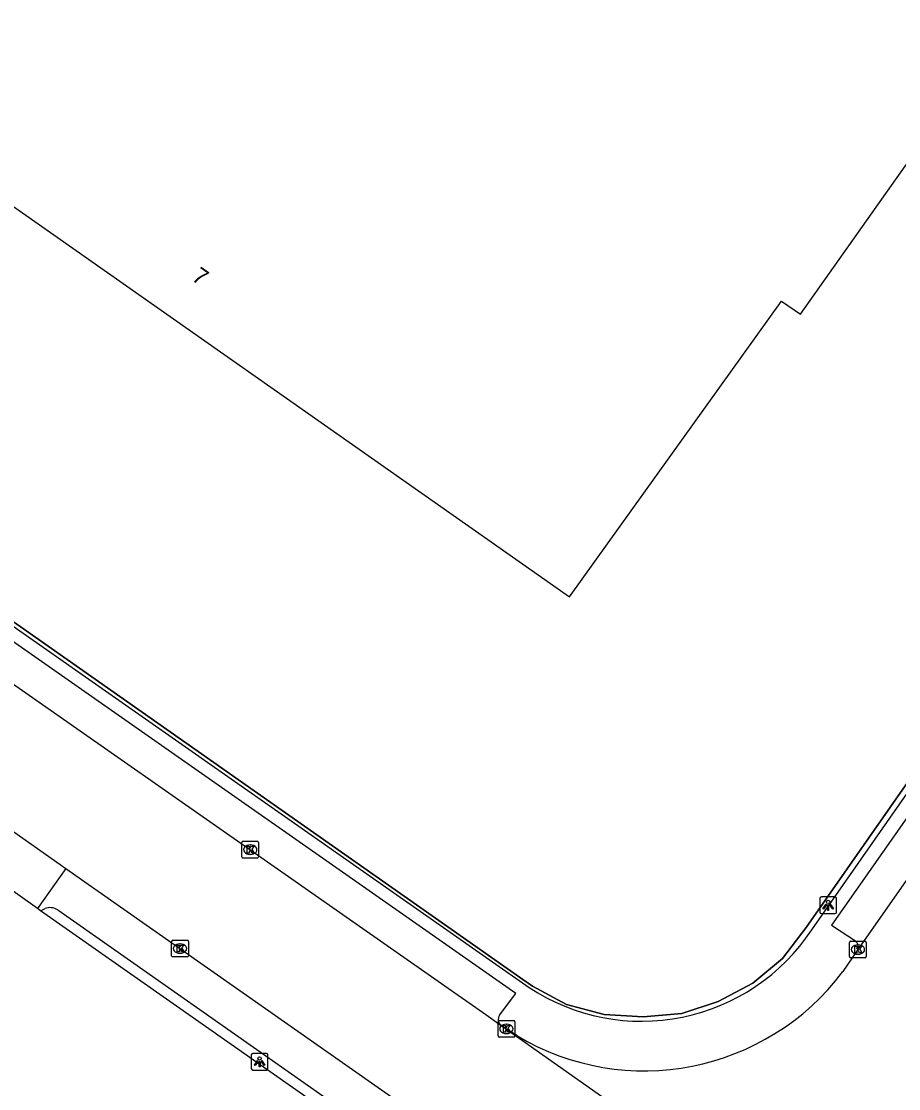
# Model space of a CAD drawing. Extents: x 155018 to 156648, y 383980 to 385733.
# Drawn here: x 155280 to 155332.5, y 384864.6 to 384928.5 of the extents above; entities that cross this region are included whole.
import ezdxf

# ---------------------------------------------------------------- set-up
doc = ezdxf.new("R2010")
doc.units = 0
for name, color, linetype in [('IMGEO_Hek', 7, 'Continuous'), ('IMGEO_Kolk', 7, 'Continuous'), ('IMGEO_Lichtpunt', 7, 'Continuous'), ('IMGEO_Pand', 7, 'Continuous'), ('IMGEO_Pand_nummerreeks', 7, 'Continuous'), ('IMGEO_Parkeervlak_open', 7, 'Continuous'), ('IMGEO_Rijbaan_lokaal_gesloten', 7, 'Continuous'), ('IMGEO_Rijbaan_lokaal_open', 7, 'Continuous'), ('IMGEO_Voetpad_open', 7, 'Continuous')]:
    doc.layers.add(name, color=color, linetype=linetype)

msp = doc.modelspace()

# ---------------------------------------------------------------- linework, layer by layer
at = {"layer": 'IMGEO_Hek'}
for points in [[(155310.058, 384871.115), (155310.625, 384870.717), (155312.665, 384869.611), (155314.915, 384869.017), (155317.252, 384868.882), (155319.559, 384869.078), (155321.747, 384869.789), (155323.807, 384870.894), (155325.598, 384872.375), (155327.011, 384874.232), (155360.91, 384922.726)], [(155247.243, 384915.217), (155310.058, 384871.115)]]:
    msp.add_lwpolyline(points, dxfattribs=at)
at = {"layer": 'IMGEO_Kolk'}
for p, q in [((155293.309, 384879.386), (155294.161, 384879.386)), ((155293.234, 384878.46), (155293.234, 384879.312)), ((155293.722, 384879.166), (155293.747, 384879.166)), ((155294.235, 384879.312), (155294.235, 384878.46)), ((155294.161, 384878.386), (155293.309, 384878.386)), ((155293.745, 384878.606), (155293.72, 384878.606)), ((155289.031, 384872.54), (155289.031, 384873.392)), ((155289.106, 384873.466), (155289.958, 384873.466)), ((155289.519, 384873.246), (155289.544, 384873.246)), ((155290.032, 384873.392), (155290.032, 384872.54)), ((155329.604, 384872.482), (155329.604, 384873.334)), ((155329.679, 384873.408), (155330.531, 384873.408)), ((155330.092, 384873.188), (155330.117, 384873.188)), ((155330.605, 384873.334), (155330.605, 384872.482)), ((155289.958, 384872.466), (155289.106, 384872.466)), ((155289.542, 384872.686), (155289.517, 384872.686)), ((155330.531, 384872.408), (155329.679, 384872.408)), ((155330.115, 384872.628), (155330.09, 384872.628)), ((155308.57, 384867.733), (155308.57, 384868.585)), ((155308.645, 384868.659), (155309.497, 384868.659)), ((155309.571, 384868.585), (155309.571, 384867.733)), ((155309.081, 384867.879), (155309.056, 384867.879)), ((155309.058, 384868.439), (155309.083, 384868.439)), ((155309.497, 384867.659), (155308.645, 384867.659))]:
    msp.add_line(p, q, dxfattribs=at)
for points in [[(155293.309, 384879.386), (155294.161, 384879.386)], [(155293.234, 384878.46), (155293.234, 384879.312)], [(155293.555, 384879.086), (155293.678, 384879.086), (155293.678, 384878.935), (155293.808, 384879.086), (155293.972, 384879.086), (155293.826, 384878.935), (155293.979, 384878.686), (155293.827, 384878.686), (155293.742, 384878.85), (155293.678, 384878.783), (155293.678, 384878.686), (155293.555, 384878.686), (155293.555, 384879.086)], [(155294.235, 384879.312), (155294.235, 384878.46)], [(155294.161, 384878.386), (155293.309, 384878.386)], [(155289.031, 384872.54), (155289.031, 384873.392)], [(155289.106, 384873.466), (155289.958, 384873.466)], [(155289.352, 384873.166), (155289.475, 384873.166), (155289.475, 384873.015), (155289.605, 384873.166), (155289.769, 384873.166), (155289.623, 384873.015), (155289.776, 384872.766), (155289.624, 384872.766), (155289.539, 384872.93), (155289.475, 384872.863), (155289.475, 384872.766), (155289.352, 384872.766), (155289.352, 384873.166)], [(155290.032, 384873.392), (155290.032, 384872.54)], [(155329.604, 384872.482), (155329.604, 384873.334)], [(155329.679, 384873.408), (155330.531, 384873.408)], [(155329.925, 384873.108), (155330.048, 384873.108), (155330.048, 384872.957), (155330.178, 384873.108), (155330.342, 384873.108), (155330.196, 384872.957), (155330.349, 384872.708), (155330.197, 384872.708), (155330.112, 384872.872), (155330.048, 384872.805), (155330.048, 384872.708), (155329.925, 384872.708), (155329.925, 384873.108)], [(155330.605, 384873.334), (155330.605, 384872.482)], [(155289.958, 384872.466), (155289.106, 384872.466)], [(155330.531, 384872.408), (155329.679, 384872.408)], [(155308.57, 384867.733), (155308.57, 384868.585)], [(155308.645, 384868.659), (155309.497, 384868.659)], [(155309.571, 384868.585), (155309.571, 384867.733)], [(155308.891, 384868.359), (155309.014, 384868.359), (155309.014, 384868.208), (155309.144, 384868.359), (155309.308, 384868.359), (155309.162, 384868.208), (155309.315, 384867.959), (155309.163, 384867.959), (155309.078, 384868.123), (155309.014, 384868.056), (155309.014, 384867.959), (155308.891, 384867.959), (155308.891, 384868.359)], [(155309.497, 384867.659), (155308.645, 384867.659)]]:
    msp.add_lwpolyline(points, dxfattribs=at)
for centre, start, end in [((155293.311, 384879.31), 91.55205, 178.44795), ((155293.311, 384879.31), 91.55205, 178.44795), ((155294.159, 384879.31), 1.55205, 88.44795), ((155294.159, 384879.31), 1.55205, 88.44795), ((155293.311, 384878.462), 181.55205, 268.44795), ((155293.311, 384878.462), 181.55205, 268.44795), ((155294.159, 384878.462), 271.55205, 358.44795), ((155294.159, 384878.462), 271.55205, 358.44795), ((155289.108, 384873.39), 91.55205, 178.44795), ((155289.108, 384873.39), 91.55205, 178.44795), ((155289.956, 384873.39), 1.55205, 88.44795), ((155289.956, 384873.39), 1.55205, 88.44795), ((155329.681, 384873.332), 91.55205, 178.44795), ((155329.681, 384873.332), 91.55205, 178.44795), ((155330.529, 384873.332), 1.55205, 88.44795), ((155330.529, 384873.332), 1.55205, 88.44795), ((155289.108, 384872.542), 181.55205, 268.44795), ((155289.108, 384872.542), 181.55205, 268.44795), ((155289.956, 384872.542), 271.55205, 358.44795), ((155289.956, 384872.542), 271.55205, 358.44795), ((155329.681, 384872.484), 181.55205, 268.44795), ((155329.681, 384872.484), 181.55205, 268.44795), ((155330.529, 384872.484), 271.55205, 358.44795), ((155330.529, 384872.484), 271.55205, 358.44795), ((155308.647, 384868.583), 91.55205, 178.44795), ((155308.647, 384868.583), 91.55205, 178.44795), ((155309.495, 384868.583), 1.55205, 88.44795), ((155309.495, 384868.583), 1.55205, 88.44795), ((155308.647, 384867.735), 181.55205, 268.44795), ((155308.647, 384867.735), 181.55205, 268.44795), ((155309.495, 384867.735), 271.55205, 358.44795), ((155309.495, 384867.735), 271.55205, 358.44795)]:
    msp.add_arc(centre, 0.0765, start, end, dxfattribs=at)
for centre, major_axis, ratio, start_param, end_param in [((155293.721, 384878.886), (-0.387, 0.002), 0.722429, 4.712389, 7.853982), ((155293.746, 384878.886), (-0.39, 0.002), 0.717154, 1.570796, 4.712389), ((155289.518, 384872.966), (-0.387, 0.002), 0.722429, 4.712389, 7.853982), ((155289.543, 384872.966), (-0.39, 0.002), 0.717154, 1.570796, 4.712389), ((155330.091, 384872.908), (-0.387, 0.002), 0.722429, 4.712389, 7.853982), ((155330.116, 384872.908), (-0.39, 0.002), 0.717154, 1.570796, 4.712389), ((155309.057, 384868.159), (-0.387, 0.002), 0.722429, 4.712389, 7.853982), ((155309.082, 384868.159), (-0.39, 0.002), 0.717154, 1.570796, 4.712389)]:
    msp.add_ellipse(centre, major_axis=major_axis, ratio=ratio, start_param=start_param, end_param=end_param, dxfattribs=at)
at = {"layer": 'IMGEO_Lichtpunt'}
for p, q in [((155327.826, 384875.959), (155327.826, 384875.152)), ((155327.826, 384875.959), (155327.826, 384875.152)), ((155328.728, 384876.054), (155327.92, 384876.054)), ((155328.728, 384876.054), (155327.92, 384876.054)), ((155328.822, 384875.152), (155328.822, 384875.959)), ((155328.822, 384875.152), (155328.822, 384875.959)), ((155327.92, 384875.058), (155328.728, 384875.058)), ((155327.92, 384875.058), (155328.728, 384875.058)), ((155293.797, 384866.595), (155293.797, 384865.788)), ((155293.797, 384866.595), (155293.797, 384865.788)), ((155294.699, 384866.69), (155293.891, 384866.69)), ((155294.699, 384866.69), (155293.891, 384866.69)), ((155294.793, 384865.788), (155294.793, 384866.595)), ((155294.793, 384865.788), (155294.793, 384866.595)), ((155293.891, 384865.694), (155294.699, 384865.694)), ((155293.891, 384865.694), (155294.699, 384865.694))]:
    msp.add_line(p, q, dxfattribs=at)
for points in [[(155328.2, 384875.623), (155328.239, 384875.595), (155328.051, 384875.333), (155328.013, 384875.36), (155328.2, 384875.623)], [(155328.302, 384875.575), (155328.349, 384875.575), (155328.349, 384875.253), (155328.302, 384875.253), (155328.302, 384875.575)], [(155328.412, 384875.595), (155328.45, 384875.622), (155328.637, 384875.36), (155328.598, 384875.332), (155328.412, 384875.595)], [(155294.171, 384866.259), (155294.21, 384866.231), (155294.022, 384865.969), (155293.984, 384865.996), (155294.171, 384866.259)], [(155294.273, 384866.211), (155294.32, 384866.211), (155294.32, 384865.889), (155294.273, 384865.889), (155294.273, 384866.211)], [(155294.383, 384866.231), (155294.421, 384866.258), (155294.608, 384865.996), (155294.569, 384865.968), (155294.383, 384866.231)]]:
    msp.add_lwpolyline(points, dxfattribs=at)
for centre in [(155328.325, 384875.757), (155294.296, 384866.393)]:
    msp.add_circle(centre, 0.0994, dxfattribs=at)
for centre, start, end in [((155327.92, 384875.959), 90, 180), ((155327.92, 384875.959), 90, 180), ((155328.728, 384875.959), 0, 90), ((155328.728, 384875.959), 0, 90), ((155327.92, 384875.152), 180, 270), ((155327.92, 384875.152), 180, 270), ((155328.728, 384875.152), 270, 0), ((155328.728, 384875.152), 270, 360), ((155293.891, 384866.595), 90, 180), ((155293.891, 384866.595), 90, 180), ((155294.699, 384866.595), 0, 90), ((155294.699, 384866.595), 0, 90), ((155293.891, 384865.788), 180, 270), ((155293.891, 384865.788), 180, 270), ((155294.699, 384865.788), 270, 0), ((155294.699, 384865.788), 270, 360)]:
    msp.add_arc(centre, 0.0946, start, end, dxfattribs=at)
at = {"layer": 'IMGEO_Pand'}
msp.add_lwpolyline([(155345.564, 384937.674), (155341.057, 384940.844), (155352.785, 384957.566), (155357.294, 384954.376), (155357.454, 384954.61), (155357.905, 384955.275), (155287.947, 385004.428), (155247.386, 384946.755), (155267.067, 384932.914), (155268.309, 384932.073), (155265.219, 384927.444), (155312.836, 384894.014), (155325.533, 384911.727), (155326.662, 384910.934), (155345.564, 384937.674)], dxfattribs=at)
at = {"layer": 'IMGEO_Parkeervlak_open'}
msp.add_lwpolyline([(155281.186, 384875.226), (155281.002, 384875.356)], dxfattribs=at)
at = {"layer": 'IMGEO_Rijbaan_lokaal_gesloten'}
for points in [[(155360.676, 384916.596), (155330.069, 384872.85)], [(155308.749, 384868.347), (155307.828, 384868.991), (155250.095, 384909.364)], [(155277.864, 384881.141), (155282.705, 384877.749)], [(155282.705, 384877.749), (155304.661, 384862.364), (155312.349, 384857.014), (155325.715, 384847.641), (155332.492, 384842.858)], [(155330.069, 384872.85), (155329.2, 384871.59)], [(155308.812, 384868.307), (155308.749, 384868.347)], [(155339.386, 384846.829), (155338.759, 384847.187), (155308.812, 384868.307)], [(155309.684, 384867.754), (155308.812, 384868.307)]]:
    msp.add_lwpolyline(points, dxfattribs=at)
msp.add_arc((155317.31, 384880.519), 14.87, 239.14667, 323.09355, dxfattribs=at)
at = {"layer": 'IMGEO_Rijbaan_lokaal_open'}
for points in [[(155360.915, 384922.733), (155360.91, 384922.726), (155327.011, 384874.232), (155325.598, 384872.375), (155323.807, 384870.894), (155321.747, 384869.789), (155319.559, 384869.078), (155317.252, 384868.882), (155314.915, 384869.017), (155312.665, 384869.611), (155310.625, 384870.717), (155310.058, 384871.115), (155247.243, 384915.217), (155232.066, 384925.988)], [(155327.339, 384874.089), (155357.86, 384917.764), (155361.028, 384922.286)], [(155247.249, 384914.872), (155310.436, 384870.637)], [(155281.002, 384875.356), (155276.212, 384878.76)], [(155282.705, 384877.749), (155281.002, 384875.356)]]:
    msp.add_lwpolyline(points, dxfattribs=at)
msp.add_arc((155317.162, 384880.812), 12.197, 236.53465, 326.55027, dxfattribs=at)
at = {"layer": 'IMGEO_Voetpad_open'}
for points in [[(155360.167, 384916.509), (155358.77, 384917.47), (155328.528, 384874.37), (155329.952, 384873.425)], [(155308.649, 384868.973), (155309.622, 384870.283), (155251.629, 384910.858), (155250.64, 384909.439)], [(155281.186, 384875.226), (155281.453, 384875.359)], [(155330.905, 384840.366), (155281.186, 384875.226)], [(155282.214, 384875.28), (155303.376, 384860.446), (155310.968, 384855.094), (155324.356, 384845.722), (155330.672, 384841.312)]]:
    msp.add_lwpolyline(points, dxfattribs=at)
for centre, radius, start, end in [((155281.756, 384874.574), 0.841, 57.03055, 111.11607), ((155329.657, 384873.066), 0.465, 332.40527, 50.59758), ((155309.064, 384868.718), 0.487, 148.47688, 229.67511)]:
    msp.add_arc(centre, radius, start, end, dxfattribs=at)

# ---------------------------------------------------------------- texts
at = {"layer": 'IMGEO_Pand_nummerreeks'}
msp.add_text('7', height=1, rotation=324.92925, dxfattribs=at).set_placement((155290.166, 384913.009))

doc.saveas('drawing.dxf')
